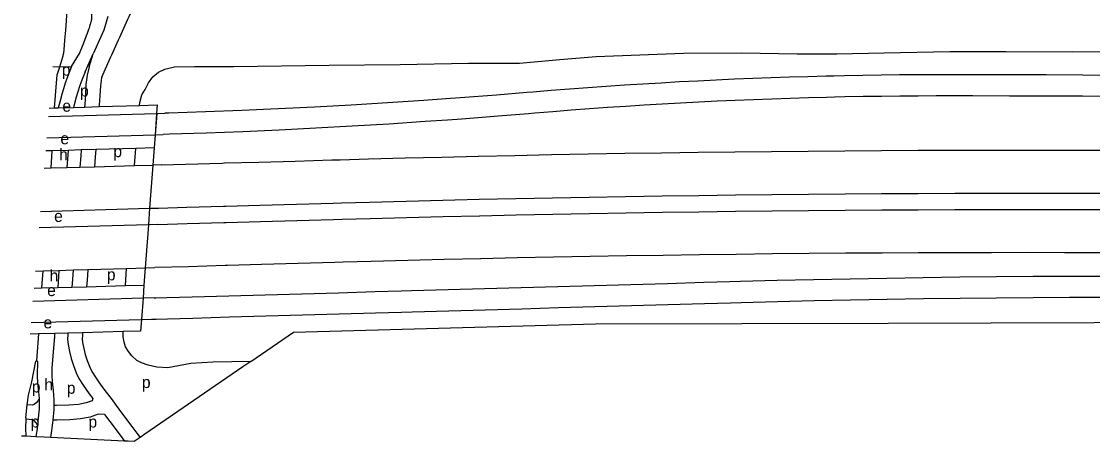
# Model space of a CAD drawing. Extents: x 160204 to 161526, y 379528 to 381793.
# Drawn here: x 160203.7 to 160569.9, y 379535.4 to 379679.1 of the extents above; entities that cross this region are included whole.
import ezdxf

# ---------------------------------------------------------------- set-up
doc = ezdxf.new("R2010")
doc.units = 0
for name, color, linetype in [('BLT_Basislijn', 7, 'Continuous'), ('BLT_Centroide', 7, 'Continuous'), ('BLT_Gemeentegrens', 7, 'Continuous'), ('BLT_Vlakafsluiter', 7, 'Continuous')]:
    doc.layers.add(name, color=color, linetype=linetype)

msp = doc.modelspace()

# ---------------------------------------------------------------- linework, layer by layer
at = {"layer": 'BLT_Basislijn'}
for p, q in [((160225.47, 379661.86), (160228.21, 379668.08)), ((160226.83, 379663.56), (160228.21, 379668.08)), ((160213.25, 379649.46), (160215.06, 379649.51)), ((160215.06, 379649.51), (160216.3, 379649.55)), ((160216.3, 379649.55), (160221.53, 379649.7)), ((160221.53, 379649.7), (160225.29, 379649.82)), ((160225.29, 379649.82), (160230.31, 379649.96)), ((160230.31, 379649.96), (160244.11, 379650.38)), ((160244.11, 379650.38), (160250.16, 379650.56)), ((160213.01, 379646.58), (160249.95, 379647.63)), ((160249.95, 379647.63), (160250, 379647.63)), ((160250, 379647.63), (160252.75, 379647.71)), ((160212.39, 379639.31), (160249.41, 379640.36)), ((160249.41, 379640.36), (160249.46, 379640.36)), ((160249.46, 379640.36), (160252.17, 379640.44)), ((160214.28, 379634.86), (160212.01, 379634.79)), ((160213.84, 379628.99), (160214.28, 379634.86)), ((160219.64, 379635.01), (160214.28, 379634.86)), ((160224.15, 379635.14), (160219.64, 379635.01)), ((160229.17, 379635.28), (160224.15, 379635.14)), ((160242.87, 379635.67), (160229.17, 379635.28)), ((160249.08, 379635.85), (160242.87, 379635.67)), ((160211.51, 379628.93), (160213.84, 379628.99)), ((160213.84, 379628.99), (160219.23, 379629.15)), ((160219.23, 379629.15), (160223.73, 379629.27)), ((160223.73, 379629.27), (160228.75, 379629.42)), ((160228.75, 379629.42), (160242.38, 379629.8)), ((160242.38, 379629.8), (160248.64, 379629.98)), ((160251.58, 379630.06), (160248.64, 379629.98)), ((160210.25, 379614.13), (160247.55, 379615.19)), ((160247.55, 379615.19), (160250.57, 379615.28)), ((160247.14, 379609.58), (160209.77, 379608.52)), ((160250.31, 379609.67), (160247.14, 379609.58)), ((160208.52, 379593.73), (160211.13, 379593.8)), ((160210.71, 379587.94), (160211.13, 379593.8)), ((160211.13, 379593.8), (160216.56, 379593.95)), ((160216.56, 379593.95), (160221.4, 379594.09)), ((160221.4, 379594.09), (160226.42, 379594.23)), ((160226.42, 379594.23), (160239.64, 379594.61)), ((160239.64, 379594.61), (160246.05, 379594.79)), ((160246.05, 379594.79), (160249.28, 379594.88)), ((160208.02, 379587.86), (160210.71, 379587.94)), ((160210.71, 379587.94), (160216.12, 379588.09)), ((160216.12, 379588.09), (160220.95, 379588.23)), ((160220.95, 379588.23), (160225.98, 379588.37)), ((160225.98, 379588.37), (160239.32, 379588.75)), ((160239.32, 379588.75), (160245.61, 379588.93)), ((160245.28, 379584.42), (160207.63, 379583.35)), ((160249.04, 379584.52), (160245.28, 379584.42)), ((160207.02, 379576.08), (160244.74, 379577.15)), ((160244.74, 379577.15), (160248.18, 379577.25)), ((160209.55, 379572.18), (160206.68, 379572.1)), ((160209.55, 379572.18), (160208.82, 379562.95)), ((160215.04, 379572.34), (160209.55, 379572.18)), ((160219.6, 379572.46), (160215.04, 379572.34)), ((160224.63, 379572.61), (160219.6, 379572.46)), ((160238.47, 379573), (160224.63, 379572.61)), ((160244.45, 379573.16), (160238.47, 379573))]:
    msp.add_line(p, q, dxfattribs=at)
for points in [[(160218.34, 379669.37), (160218.6, 379672.73), (160218.86, 379676.08), (160219.13, 379679.44), (160219.39, 379682.8), (160219.66, 379686.16), (160219.92, 379689.51), (160220.19, 379692.87), (160220.45, 379696.23), (160220.72, 379699.58), (160220.98, 379702.94), (160221.24, 379706.3), (160221.51, 379709.65), (160221.77, 379713.01), (160222.04, 379716.37), (160222.3, 379719.73), (160222.57, 379723.08), (160222.83, 379726.44), (160223.1, 379729.8), (160223.36, 379733.15)], [(160227.58, 379679.01), (160227.62, 379679.16), (160227.66, 379679.31), (160227.7, 379679.46), (160227.73, 379679.61), (160227.76, 379679.77), (160227.78, 379679.92), (160227.8, 379680.08), (160227.82, 379680.23), (160227.83, 379680.39), (160227.83, 379680.55), (160227.83, 379680.7), (160227.82, 379680.86), (160227.82, 379681.02), (160227.8, 379681.17), (160227.78, 379681.33), (160227.76, 379681.48), (160227.73, 379681.64), (160227.7, 379681.79), (160227.66, 379681.94)], [(160231.17, 379660.05), (160233.73, 379665.71), (160234.19, 379666.72), (160234.64, 379667.73), (160235.1, 379668.74), (160235.55, 379669.75), (160236.01, 379670.76), (160236.47, 379671.76), (160236.92, 379672.77), (160237.38, 379673.78), (160237.84, 379674.79), (160238.29, 379675.8), (160238.75, 379676.81), (160239.2, 379677.82), (160239.66, 379678.83), (160240.12, 379679.84), (160240.57, 379680.85), (160241.03, 379681.86), (160241.49, 379682.86), (160241.96, 379683.92)], [(160220.81, 379663.68), (160223.53, 379668.09), (160224.77, 379671.2), (160225.73, 379673.62), (160226.01, 379674.35), (160226.29, 379675.09), (160226.57, 379675.82), (160226.78, 379676.42), (160226.94, 379676.92), (160227.11, 379677.43), (160227.27, 379677.94), (160227.36, 379678.25), (160227.43, 379678.5), (160227.5, 379678.76), (160227.58, 379679.01)], [(160233.2, 379680.77), (160231.84, 379676.14), (160228.21, 379668.08)], [(160216.89, 379663.58), (160217.9, 379667.02), (160217.93, 379667.15), (160217.96, 379667.27), (160217.98, 379667.39), (160218.01, 379667.51), (160218.04, 379667.64), (160218.07, 379667.76), (160218.09, 379667.88), (160218.12, 379668.01), (160218.14, 379668.13), (160218.16, 379668.25), (160218.19, 379668.38), (160218.21, 379668.5), (160218.23, 379668.62), (160218.25, 379668.75), (160218.27, 379668.87), (160218.29, 379669), (160218.3, 379669.12), (160218.32, 379669.25), (160218.34, 379669.37)], [(160250.56, 379661.72), (160252.71, 379662.8), (160256, 379663.55), (160262.83, 379663.66), (160276.24, 379663.71), (160308.89, 379664.14), (160333.19, 379664.33), (160356.55, 379664.8), (160374.01, 379664.78), (160387.74, 379666.07), (160400.17, 379667.09), (160430.1, 379668.26), (160449.88, 379668.36), (160468.94, 379667.97), (160482.5, 379668.07), (160498.63, 379668.33), (160521.07, 379668.87), (160540.29, 379668.82), (160563.17, 379668.7), (160589.01, 379668.81)], [(160215.06, 379649.51), (160215.94, 379660.87), (160216.89, 379663.58)], [(160220.81, 379663.68), (160219.46, 379660.21), (160218.81, 379658.37), (160217.64, 379654.61), (160216.84, 379651.47), (160216.3, 379649.55)], [(160226.83, 379663.56), (160226.19, 379660.68), (160225.76, 379657.49), (160225.57, 379654), (160225.36, 379650.76), (160225.29, 379649.82)], [(160225.47, 379661.86), (160224.15, 379658.47), (160223.56, 379656.8), (160222.46, 379653.24), (160221.66, 379650.16), (160221.53, 379649.7)], [(160231.17, 379660.05), (160231.12, 379659.81), (160230.74, 379657.03), (160230.56, 379653.7), (160230.35, 379650.41), (160230.31, 379649.96)], [(160244.11, 379650.38), (160244.19, 379651.37), (160244.86, 379653.97), (160245.99, 379655.85), (160247.12, 379658.06), (160248.62, 379660.11), (160250.56, 379661.72)], [(160579.02, 379660.66), (160566.51, 379660.74), (160554, 379660.81), (160541.49, 379660.85), (160528.98, 379660.88), (160521.81, 379660.89), (160516.45, 379660.88), (160510.17, 379660.85), (160503.9, 379660.8), (160497.62, 379660.73), (160491.35, 379660.63), (160485.08, 379660.51), (160481.45, 379660.43), (160478.8, 379660.37), (160472.53, 379660.2), (160466.26, 379660.01), (160459.99, 379659.8), (160453.72, 379659.57), (160447.45, 379659.31), (160441.18, 379659.03), (160434.91, 379658.72), (160428.64, 379658.39), (160422.38, 379658.04), (160416.11, 379657.67), (160409.85, 379657.27), (160403.59, 379656.85), (160397.33, 379656.41), (160391.07, 379655.95), (160384.82, 379655.46), (160378.56, 379654.95), (160376.49, 379654.77), (160366.13, 379653.92), (160353.7, 379652.95), (160348.8, 379652.59), (160341.27, 379652.06), (160328.84, 379651.24), (160316.4, 379650.48), (160303.96, 379649.8), (160291.51, 379649.18), (160279.06, 379648.63), (160266.61, 379648.16), (160254.15, 379647.75), (160252.75, 379647.71)], [(160578.96, 379653.41), (160566.46, 379653.49), (160553.96, 379653.56), (160541.46, 379653.6), (160528.97, 379653.63), (160521.81, 379653.64), (160516.47, 379653.63), (160510.22, 379653.6), (160503.97, 379653.55), (160497.72, 379653.48), (160491.48, 379653.38), (160485.23, 379653.26), (160481.62, 379653.18), (160478.98, 379653.12), (160472.74, 379652.96), (160466.49, 379652.77), (160460.24, 379652.56), (160454, 379652.32), (160447.76, 379652.06), (160441.52, 379651.78), (160435.27, 379651.48), (160429.04, 379651.16), (160422.8, 379650.81), (160416.56, 379650.43), (160410.32, 379650.04), (160404.09, 379649.62), (160397.86, 379649.18), (160391.63, 379648.72), (160385.4, 379648.23), (160379.17, 379647.72), (160377.1, 379647.55), (160366.71, 379646.69), (160354.24, 379645.72), (160349.33, 379645.36), (160341.77, 379644.83), (160329.3, 379644), (160316.82, 379643.25), (160304.34, 379642.56), (160291.85, 379641.94), (160279.36, 379641.39), (160266.86, 379640.91), (160254.37, 379640.5), (160252.17, 379640.44)], [(160250.16, 379650.56), (160249.95, 379647.63)], [(160249.41, 379640.36), (160249.08, 379635.85)], [(160219.64, 379635.01), (160219.45, 379631.98), (160219.23, 379629.15)], [(160224.15, 379635.14), (160223.99, 379633.11), (160223.73, 379629.27)], [(160229.17, 379635.28), (160228.98, 379632.75), (160228.75, 379629.42)], [(160242.38, 379629.8), (160242.87, 379635.67)], [(160249.08, 379635.85), (160248.64, 379629.98)], [(160251.58, 379630.06), (160259.86, 379630.3), (160272.35, 379630.65), (160273.17, 379630.68), (160284.85, 379631.01), (160297.34, 379631.36), (160309.83, 379631.72), (160312.73, 379631.8), (160322.35, 379632.07), (160334.87, 379632.4), (160347.4, 379632.71), (160359.8, 379633), (160359.92, 379633), (160372.44, 379633.28), (160384.97, 379633.53), (160397.49, 379633.77), (160410.02, 379633.99), (160422.54, 379634.18), (160435.07, 379634.36), (160447.59, 379634.52), (160460.12, 379634.66), (160472.65, 379634.78), (160485.17, 379634.89), (160497.7, 379634.97), (160510.22, 379635.03), (160522.75, 379635.08), (160535.28, 379635.1), (160547.8, 379635.11), (160560.33, 379635.1), (160572.86, 379635.07)], [(160250.57, 379615.28), (160260.27, 379615.55), (160272.77, 379615.91), (160273.58, 379615.93), (160285.26, 379616.26), (160297.76, 379616.62), (160310.25, 379616.97), (160313.15, 379617.06), (160322.75, 379617.32), (160335.25, 379617.65), (160347.75, 379617.97), (160360.14, 379618.26), (160360.25, 379618.26), (160372.75, 379618.53), (160385.26, 379618.79), (160397.76, 379619.02), (160410.26, 379619.24), (160422.76, 379619.44), (160435.27, 379619.61), (160447.77, 379619.77), (160460.27, 379619.91), (160472.78, 379620.03), (160485.28, 379620.14), (160497.78, 379620.22), (160510.29, 379620.28), (160522.79, 379620.33), (160535.3, 379620.35), (160547.8, 379620.36), (160560.31, 379620.35), (160572.81, 379620.32)], [(160247.55, 379615.19), (160247.14, 379609.58)], [(160250.31, 379609.67), (160260.43, 379609.96), (160272.93, 379610.31), (160273.74, 379610.33), (160285.42, 379610.67), (160297.92, 379611.02), (160310.41, 379611.38), (160313.31, 379611.46), (160322.9, 379611.72), (160335.4, 379612.06), (160347.89, 379612.37), (160360.27, 379612.66), (160360.38, 379612.66), (160372.87, 379612.93), (160385.37, 379613.19), (160397.86, 379613.42), (160410.35, 379613.64), (160422.85, 379613.84), (160435.34, 379614.01), (160447.84, 379614.17), (160460.33, 379614.31), (160472.83, 379614.43), (160485.32, 379614.54), (160497.82, 379614.62), (160510.31, 379614.68), (160522.81, 379614.73), (160535.3, 379614.75), (160547.8, 379614.76), (160560.3, 379614.75), (160572.79, 379614.72)], [(160572.74, 379599.97), (160560.27, 379600), (160547.8, 379600.01), (160535.32, 379600), (160522.85, 379599.98), (160510.38, 379599.93), (160497.9, 379599.87), (160485.43, 379599.79), (160472.96, 379599.68), (160460.49, 379599.56), (160448.01, 379599.42), (160435.54, 379599.27), (160423.07, 379599.09), (160410.6, 379598.89), (160398.13, 379598.67), (160385.65, 379598.44), (160373.18, 379598.19), (160360.71, 379597.91), (160360.6, 379597.91), (160348.24, 379597.62), (160335.77, 379597.31), (160323.31, 379596.98), (160313.73, 379596.71), (160310.83, 379596.63), (160298.34, 379596.28), (160285.84, 379595.92), (160274.16, 379595.59), (160273.35, 379595.57), (160260.85, 379595.21), (160249.28, 379594.88)], [(160216.56, 379593.95), (160216.24, 379589.86), (160216.12, 379588.09)], [(160221.4, 379594.09), (160221.18, 379590.86), (160220.95, 379588.23)], [(160226.42, 379594.23), (160226.17, 379590.48), (160225.98, 379588.37)], [(160239.32, 379588.75), (160239.64, 379594.61)], [(160246.05, 379594.79), (160245.61, 379588.93)], [(160249.04, 379584.52), (160249.61, 379584.54), (160253.4, 379584.65), (160262.1, 379584.89), (160274.6, 379585.25), (160287.09, 379585.6), (160299.59, 379585.96), (160312.08, 379586.31), (160324.58, 379586.67), (160333.5, 379586.92), (160337.07, 379587.02), (160349.57, 379587.38), (160362.06, 379587.73), (160374.56, 379588.09), (160387.05, 379588.44), (160399.55, 379588.8), (160412.04, 379589.15), (160424.54, 379589.51), (160437.03, 379589.86), (160445.92, 379590.11), (160449.53, 379590.21), (160462.03, 379590.54), (160474.52, 379590.84), (160487.02, 379591.1), (160499.52, 379591.33), (160512.02, 379591.53), (160524.52, 379591.69), (160537.02, 379591.83), (160549.52, 379591.92), (160562.02, 379591.99), (160574.52, 379592.02)], [(160245.61, 379588.93), (160245.28, 379584.42)], [(160248.18, 379577.25), (160249.81, 379577.29), (160253.61, 379577.4), (160262.31, 379577.65), (160274.8, 379578), (160287.3, 379578.36), (160299.79, 379578.71), (160312.29, 379579.07), (160324.78, 379579.42), (160333.7, 379579.67), (160337.28, 379579.78), (160349.77, 379580.13), (160362.27, 379580.49), (160374.76, 379580.84), (160387.26, 379581.19), (160399.75, 379581.55), (160412.25, 379581.9), (160424.74, 379582.26), (160437.24, 379582.61), (160446.12, 379582.87), (160449.73, 379582.97), (160462.21, 379583.3), (160474.69, 379583.59), (160487.16, 379583.85), (160499.64, 379584.08), (160512.13, 379584.28), (160524.61, 379584.44), (160537.09, 379584.58), (160549.57, 379584.67), (160562.05, 379584.74), (160574.53, 379584.77)], [(160244.74, 379577.15), (160244.45, 379573.16)], [(160215.04, 379572.34), (160214.97, 379571.25), (160214.59, 379566.07), (160214.16, 379560.44), (160214.12, 379557.95), (160214.21, 379555.89), (160214.53, 379552.83), (160214.79, 379549.66), (160214.77, 379547.68)], [(160219.6, 379572.46), (160219.56, 379572.02), (160219.48, 379570.35), (160219.7, 379568.53), (160220.13, 379566.2), (160220.72, 379563.83), (160221.47, 379561.44), (160222.46, 379558.84), (160223.37, 379556.95), (160224.83, 379554.62), (160226.84, 379551.76), (160228.13, 379550.08)], [(160224.63, 379572.61), (160224.55, 379571.7), (160224.5, 379570.54), (160224.65, 379569.28), (160225.02, 379567.25), (160225.54, 379565.19), (160226.2, 379563.08), (160227.06, 379560.82), (160227.76, 379559.37), (160229, 379557.39), (160230.87, 379554.71), (160232.7, 379552.33), (160234.34, 379550.07), (160236.15, 379547.67), (160237.94, 379545.25)], [(160282.09, 379562.78), (160269.11, 379562.54), (160261.68, 379562.06), (160253.77, 379560.6), (160249.96, 379560.78), (160247.06, 379561.49), (160244.76, 379562.29), (160243.16, 379563.12), (160241.47, 379564.7), (160240.31, 379566.23), (160239.32, 379567.8), (160238.8, 379569.37), (160238.52, 379571.16), (160238.46, 379572.76), (160238.47, 379573)], [(160205.67, 379547.99), (160205.75, 379548.78), (160206.19, 379551.28), (160207.25, 379555.8), (160208.69, 379562.93), (160208.82, 379562.95)], [(160208.82, 379562.95), (160209.21, 379562.92), (160209.12, 379557.89), (160209.22, 379555.52), (160209.55, 379552.36), (160209.74, 379550.15)], [(160209.74, 379550.15), (160209.41, 379549.41), (160208.79, 379548.61), (160208.13, 379548.09), (160207.35, 379547.87), (160205.67, 379547.99)], [(160228.13, 379550.08), (160227.93, 379549.36), (160225.85, 379548.61), (160223.27, 379548.1), (160219.96, 379547.83), (160215.73, 379547.67), (160214.77, 379547.68)], [(160205.21, 379543.01), (160205.11, 379539.91), (160205.19, 379537.19)], [(160209.21, 379540.97), (160208.79, 379541.83), (160208.1, 379542.57), (160207.53, 379542.84), (160205.21, 379543.01)], [(160214.43, 379542.69), (160214.35, 379541.83), (160214.02, 379539.12)], [(160232.14, 379544.68), (160230, 379544.77), (160227.18, 379543.78), (160223.96, 379543.14), (160220.26, 379542.84), (160215.8, 379542.67), (160214.43, 379542.69)], [(160232.14, 379544.68), (160233.91, 379542.28)], [(160233.91, 379542.28), (160237.49, 379537.58), (160238.97, 379535.53)], [(160237.94, 379545.25), (160241.5, 379540.56), (160243.21, 379538.2), (160244.3, 379536.77)], [(160209.07, 379539.82), (160208.62, 379537.02)], [(160209.21, 379540.97), (160209.07, 379539.82)], [(160214.02, 379539.12), (160213.64, 379536.78)]]:
    msp.add_lwpolyline(points, dxfattribs=at)
at = {"layer": 'BLT_Gemeentegrens'}
for p, q in [((160208.62, 379537.02), (160205.19, 379537.19)), ((160238.97, 379535.53), (160213.64, 379536.78))]:
    msp.add_line(p, q, dxfattribs=at)
for points in [[(160282.09, 379562.78), (160296.67, 379572.82), (160400, 379575.68), (160500, 379575.91), (160640.86, 379576.3), (160642.65, 379576.29)], [(160282.09, 379562.78), (160279.42, 379560.95), (160245.95, 379537.9), (160244.69, 379537.04), (160244.3, 379536.77)], [(160205.19, 379537.19), (160203.94, 379537.25), (160203.72, 379537.26)], [(160213.64, 379536.78), (160211.49, 379536.88), (160208.62, 379537.02)], [(160244.3, 379536.77), (160242.27, 379535.37), (160240.17, 379535.47), (160239.59, 379535.5), (160238.97, 379535.53)]]:
    msp.add_lwpolyline(points, dxfattribs=at)
at = {"layer": 'BLT_Vlakafsluiter'}
for p, q in [((160214.46, 379663.69), (160216.89, 379663.58)), ((160216.89, 379663.58), (160220.81, 379663.68)), ((160249.95, 379647.63), (160249.41, 379640.36)), ((160250, 379647.63), (160249.46, 379640.36)), ((160248.64, 379629.98), (160247.55, 379615.19)), ((160247.14, 379609.58), (160246.05, 379594.79)), ((160245.28, 379584.42), (160244.74, 379577.15))]:
    msp.add_line(p, q, dxfattribs=at)
for points in [[(160209.74, 379550.15), (160209.79, 379549.48), (160209.76, 379546.62), (160209.38, 379542.36), (160209.21, 379540.97)], [(160205.22, 379543.51), (160205.67, 379547.99)], [(160214.77, 379547.68), (160214.76, 379546.37), (160214.43, 379542.69)], [(160205.22, 379543.51), (160205.21, 379543.01)]]:
    msp.add_lwpolyline(points, dxfattribs=at)

# ---------------------------------------------------------------- texts
at = {"layer": 'BLT_Centroide'}
for s, p in [('p', (160217.52, 379660.57)), ('p', (160223.75, 379653.42)), ('e', (160217.71, 379648.23)), ('e', (160217.05, 379637.09)), ('h', (160216.6, 379631.58)), ('p', (160235.14, 379632.69)), ('e', (160214.9, 379610.52)), ('h', (160213.35, 379590.14)), ('p', (160232.92, 379590.53)), ('e', (160212.52, 379585.15)), ('e', (160211.26, 379574.11)), ('h', (160211.55, 379552.91)), ('p', (160207.27, 379552.18)), ('p', (160219.23, 379551.74)), ('p', (160244.9, 379553.7)), ('p', (160206.9, 379540.19)), ('p', (160226.63, 379540.17))]:
    msp.add_text(s, height=4, dxfattribs=at).set_placement(p)

doc.saveas('drawing.dxf')
